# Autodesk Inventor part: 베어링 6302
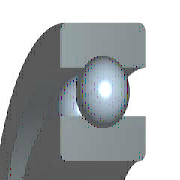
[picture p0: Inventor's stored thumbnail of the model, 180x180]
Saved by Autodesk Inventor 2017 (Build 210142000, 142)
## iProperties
IsCustomPart: 1
Created: 2012-02
Part Number: 베어링 6302
Material: 강철, 연강
Document SubType Name: Modeling
Standard: JIS B 1521
Designer: mdu-01
Standards Organization: JIS
Language: ko-KR
Size Designation: 6302 15x42x13
Categories: <MemberInstance><Categories><Category DisplayName="샤프트 부품" InternalName="7f7aeb1f-a693-4053-b835-cee3144e0d98" Mnemonic="SHFT"><Category DisplayName="베어링" Inter
Density: 1 g/cm^3
Appearance: 노란색
Author: mdu-01
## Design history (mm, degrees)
sketch "스케치" dims "d0" = 7.02 (= -0.26 x WD + 0.26 x BD)
  geometry: L1 (2.99, 14.25)-(10.01, 14.25); L2 (6.5, 14.25)-(6.5, 10.74); L3 (6.5, 14.25)-(6.5, 17.76); L4 (3.892, 11.901)-(0, 11.901); L5 (0, 7.5)-(13, 7.5); L6 (3.892, 16.599)-(0, 16.599); L7 (0, 21)-(13, 21); L8 (13, 7.5)-(13, 11.901); L9 (9.108, 11.901)-(13, 11.901); L10 (9.108, 16.599)-(13, 16.599); L11 (13, 21)-(13, 16.599); L12 (-1.4, 0)-(8.4, 0) reference; L13 (0, -0.3)-(0, 5.3) reference
  constraints: 22 end point, 4 point on line, 2 collinear, 2 perpendicular, 2 symmetric about line, 1 midpoint, 1 parallel, 14 other
  dimensions: "d9" = 15 diameter of L5 L12 (= WD); "d11" = 42 diameter of L7 L12 (= BD); "d12" = 13 distance between parallel lines of L8 L13 (= KB); "d13" = 23.802 diameter of L9 L12 (= 0.326 x BD + 0.674 x WD)
revolve "본체" stored, may be unused: angle "d6" = 90 deg
revolve "볼" stored, may be unused: angle "d7" = 90 deg
pattern_circular "IDS_ARRAYBALL[SIMPL:T]" dims angle "d3" = 360 deg
body "Solid1"
fillet "모깎기1" dims "d1" = 1 (= KRS)
other parameters: "WD" = 15 [user parameter; used in 5 equation terms], "BD" = 42 [user parameter; used in 5 equation terms], "KB" = 13 [user parameter; used in 1 equation term], "KRS" = 1 [user parameter; used in 1 equation term], "d4" = 0, "d5" = 0, "d8" = 0, "d14" = 0, "d15" = 0, "BBA" = 0 [user parameter], "BC0" = 5400000 [user parameter], "BC" = 1.14e+07 [user parameter], "BR" = 21 (= 0.5 x BD) [user parameter], "WR" = 7.5 (= 0.5 x WD) [user parameter]
